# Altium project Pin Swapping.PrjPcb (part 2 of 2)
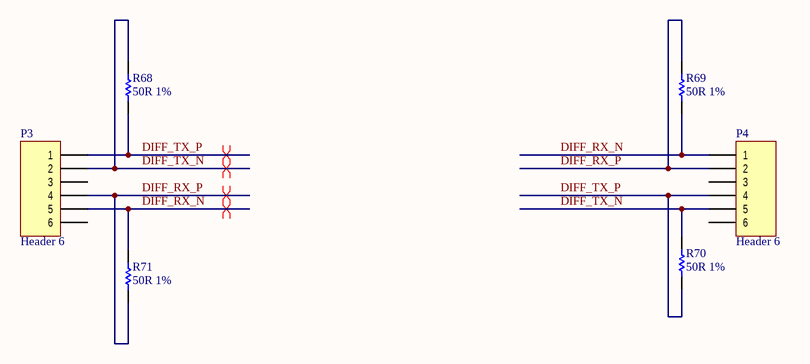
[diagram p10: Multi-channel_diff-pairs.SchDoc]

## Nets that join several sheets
+5V: TOP_SHEET (6 pins), FPGA (HDR1.97 HDR1.99 HDR2.97 HDR2.99)
GND: TOP_SHEET (14 pins), PROCESSOR (72 pins), PROCESSOR_MEMORIES (38 pins), FPGA (112 pins), FPGA_MEMORIES (14 pins)
VCC1V2: TOP_SHEET (5 pins), FPGA (26 pins)
VCC1V8: TOP_SHEET (C132.1 C133.1), PROCESSOR (22 pins), FPGA (5 pins)
VCC2V5: TOP_SHEET (8 pins), FPGA (18 pins)
VCC3V3: TOP_SHEET (C126.1 C127.1), PROCESSOR (75 pins), PROCESSOR_MEMORIES (37 pins), FPGA (77 pins), FPGA_MEMORIES (14 pins)
A0: PROCESSOR (U5.32), PROCESSOR_MEMORIES (U7.H7 U9.H7), FPGA (U1.H2)
A1: PROCESSOR (U5.31), PROCESSOR_MEMORIES (U7.H8 U8.G2 U9.H8), FPGA (U1.R19)
A2: PROCESSOR (U5.30), PROCESSOR_MEMORIES (U7.J8 U8.F2 U9.J8), FPGA (U1.P19)
A3: PROCESSOR (U5.29), PROCESSOR_MEMORIES (U7.J7 U8.E2 U9.J7), FPGA (U1.N18)
A4: PROCESSOR (U5.27), PROCESSOR_MEMORIES (U7.J3 U8.C2 U9.J3), FPGA (U1.K17)
A5: PROCESSOR (U5.26), PROCESSOR_MEMORIES (U7.J2 U8.D2 U9.J2), FPGA (U1.N21)
A6: PROCESSOR (U5.25), PROCESSOR_MEMORIES (U7.H3 U8.F3 U9.H3), FPGA (U1.P18)
A7: PROCESSOR (U5.24), PROCESSOR_MEMORIES (U7.H2 U8.E3 U9.H2), FPGA (U1.P22)
A8: PROCESSOR (U5.22), PROCESSOR_MEMORIES (U7.H1 U8.C3 U9.H1), FPGA (U1.L20)
A9: PROCESSOR (U5.21), PROCESSOR_MEMORIES (U7.G3 U8.D6 U9.G3), FPGA (U1.N20)
A10: PROCESSOR (U5.20), PROCESSOR_MEMORIES (U7.H9 U8.C6 U9.H9), FPGA (U1.K4)
A11: PROCESSOR (U5.19), PROCESSOR_MEMORIES (U7.G2 U8.E6 U9.G2), FPGA (U1.M2)
A12: PROCESSOR (U5.17), PROCESSOR_MEMORIES (U7.G1 U8.F6 U9.G1), FPGA (U1.N5)
A13: PROCESSOR (U5.16), PROCESSOR_MEMORIES (U7.G7 U8.D7 U9.G7), FPGA (U1.N17)
A14: PROCESSOR (U5.15), PROCESSOR_MEMORIES (U7.G8 U8.C7 U9.G8), FPGA (U1.N22)
A15: PROCESSOR (U5.14), PROCESSOR_MEMORIES (U8.E7), FPGA (U1.M6)
A16: PROCESSOR (U5.12), PROCESSOR_MEMORIES (U8.F7), FPGA (U1.P17)
A17: PROCESSOR (U5.11), PROCESSOR_MEMORIES (U8.G7), FPGA (U1.T19)
A18: PROCESSOR (U5.10), PROCESSOR_MEMORIES (U8.D3), FPGA (U1.M18)
A19: PROCESSOR (U5.9), PROCESSOR_MEMORIES (U8.E4), FPGA (U1.P21)
A20: PROCESSOR (U5.7), PROCESSOR_MEMORIES (U8.F5), FPGA (U1.R21)
A21: PROCESSOR (U5.6), PROCESSOR_MEMORIES (U8.F4), FPGA (U1.R22)
A22: PROCESSOR (U5.5), PROCESSOR_MEMORIES (U8.E5), FPGA (U1.N19)
A23: PROCESSOR (U5.4), FPGA (U1.F16)
A24: PROCESSOR (U5.3), FPGA (U1.D18)
A25: PROCESSOR (U5.2), FPGA (U1.F12)
CLK_RTC: PROCESSOR (R44.2), FPGA (U1.J18)
CLKIN: PROCESSOR (R36.2), FPGA (U1.J17)
CLKOUT: PROCESSOR (U5.156), FPGA (U1.D22)
D0: PROCESSOR (U5.87), PROCESSOR_MEMORIES (U8.G3 U9.A8), FPGA (U1.R18)
D1: PROCESSOR (U5.86), PROCESSOR_MEMORIES (U8.K3 U9.B9), FPGA (U1.V22)
D2: PROCESSOR (U5.84), PROCESSOR_MEMORIES (U8.G4 U9.B8), FPGA (U1.T22)
D3: PROCESSOR (U5.83), PROCESSOR_MEMORIES (U8.K4 U9.C9), FPGA (U1.V21)
D4: PROCESSOR (U5.82), PROCESSOR_MEMORIES (U8.K5 U9.C8), FPGA (U1.U14)
D5: PROCESSOR (U5.81), PROCESSOR_MEMORIES (U8.G5 U9.D9), FPGA (U1.T21)
D6: PROCESSOR (U5.79), PROCESSOR_MEMORIES (U8.K6 U9.D8), FPGA (U1.V20)
D7: PROCESSOR (U5.78), PROCESSOR_MEMORIES (U8.G6 U9.E9), FPGA (U1.T20)
D8: PROCESSOR (U5.77), PROCESSOR_MEMORIES (U8.H3 U9.E1), FPGA (U1.T18)
D9: PROCESSOR (U5.76), PROCESSOR_MEMORIES (U8.J3 U9.D2), FPGA (U1.U20)
D10: PROCESSOR (U5.74), PROCESSOR_MEMORIES (U8.H4 U9.D1), FPGA (U1.T17)
D11: PROCESSOR (U5.73), PROCESSOR_MEMORIES (U8.J4 U9.C2), FPGA (U1.U19)
D12: PROCESSOR (U5.72), PROCESSOR_MEMORIES (U8.H5 U9.C1), FPGA (U1.R4)
D13: PROCESSOR (U5.71), PROCESSOR_MEMORIES (U8.J6 U9.B2), FPGA (U1.P6)
D14: PROCESSOR (U5.69), PROCESSOR_MEMORIES (U8.H6 U9.B1), FPGA (U1.U21)
D15: PROCESSOR (U5.68), PROCESSOR_MEMORIES (U8.J7 U9.A2), FPGA (U1.U18)
D16: PROCESSOR (U5.67), PROCESSOR_MEMORIES (U7.A8), FPGA (U1.K19)
D17: PROCESSOR (U5.66), PROCESSOR_MEMORIES (U7.B9), FPGA (U1.M22)
D18: PROCESSOR (U5.65), PROCESSOR_MEMORIES (U7.B8), FPGA (U1.K22)
D19: PROCESSOR (U5.63), PROCESSOR_MEMORIES (U7.C9), FPGA (U1.M19)
D20: PROCESSOR (U5.62), PROCESSOR_MEMORIES (U7.C8), FPGA (U1.K21)
D21: PROCESSOR (U5.61), PROCESSOR_MEMORIES (U7.D9), FPGA (U1.J2)
D22: PROCESSOR (U5.60), PROCESSOR_MEMORIES (U7.D8), FPGA (U1.K6)
D23: PROCESSOR (U5.59), PROCESSOR_MEMORIES (U7.E9), FPGA (U1.M20)
D24: PROCESSOR (U5.58), PROCESSOR_MEMORIES (U7.E1), FPGA (U1.V19)
D25: PROCESSOR (U5.57), PROCESSOR_MEMORIES (U7.D2), FPGA (U1.K5)
D26: PROCESSOR (U5.56), PROCESSOR_MEMORIES (U7.D1), FPGA (U1.K18)
D27: PROCESSOR (U5.54), PROCESSOR_MEMORIES (U7.C2), FPGA (U1.L18)
D28: PROCESSOR (U5.53), PROCESSOR_MEMORIES (U7.C1), FPGA (U1.L17)
D29: PROCESSOR (U5.52), PROCESSOR_MEMORIES (U7.B2), FPGA (U1.K2)
D30: PROCESSOR (U5.51), PROCESSOR_MEMORIES (U7.B1), FPGA (U1.M21)
D31: PROCESSOR (U5.50), PROCESSOR_MEMORIES (U7.A2), FPGA (U1.L22)
FLASH_BUSY: PROCESSOR (R20.1 U5.114), PROCESSOR_MEMORIES (U8.C4)
FPGA_TCK: PROCESSOR (U6.11), FPGA (HDR1.72 R12.1)
FPGA_TMS: PROCESSOR (U6.14), FPGA (HDR1.70 R13.1)
nBLE0: PROCESSOR (U5.37), FPGA (U1.H21)
nBLE1: PROCESSOR (U5.36), FPGA (U1.J6)
nBLE2: PROCESSOR (U5.35), FPGA (U1.J1)
nBLE3: PROCESSOR (U5.34), FPGA (U1.G22)
nCS0: PROCESSOR (U5.48), FPGA (U1.L21)
nCS1: PROCESSOR (U5.47), FPGA (U1.L4)
nCS2: PROCESSOR (U5.46), FPGA (U1.L3)
nCS3: PROCESSOR (U5.44), FPGA (U1.K20)
nCS4: PROCESSOR (U5.43), FPGA (U1.J22)
nCS5: PROCESSOR (U5.42), FPGA (U1.J21)
nFLASH_CS: PROCESSOR (U5.41), PROCESSOR_MEMORIES (U8.H2)
nOE: PROCESSOR (U5.38), PROCESSOR_MEMORIES (U8.J2), FPGA (U1.H22)
nRESETOUT: PROCESSOR (U5.97), PROCESSOR_MEMORIES (U8.D5)
nSDRAM_CAS: PROCESSOR (U5.108), PROCESSOR_MEMORIES (U7.F7 U9.F7)
nSDRAM_CS: PROCESSOR (U5.105), PROCESSOR_MEMORIES (U7.G9 U9.G9)
nSDRAM_RAS: PROCESSOR (U5.107), PROCESSOR_MEMORIES (U7.F8 U9.F8)
nSDRAM_WE: PROCESSOR (U5.106), PROCESSOR_MEMORIES (U7.F9 U9.F9)
nWAIT: PROCESSOR (U5.144), FPGA (U1.J19)
nWE: PROCESSOR (U5.39), PROCESSOR_MEMORIES (U8.C5), FPGA (U1.L19)
PRO_P.SSPCLK: PROCESSOR (U5.165), FPGA (U1.E20)
PRO_P.SSPEN: PROCESSOR (U5.166), FPGA (U1.D21)
PRO_P.SSPFRM: PROCESSOR (U5.164), FPGA (U1.G17)
PRO_P.SSPRX_UART2RX: PROCESSOR (U5.169), FPGA (U1.D17)
PRO_P.SSPTX_UART2TX: PROCESSOR (U5.167), FPGA (U1.C21)
PROCESSOR_TDI: PROCESSOR (U6.3 U6.5), FPGA (R1.2 U1.B22)
PROCESSOR_TDO: PROCESSOR (U6.4), FPGA (R6.1)
SDRAM_CKE: PROCESSOR (U5.102), PROCESSOR_MEMORIES (U7.F3 U9.F3)
SDRAM_CLK: PROCESSOR (U5.101), PROCESSOR_MEMORIES (U7.F2 U9.F2)
SDRAM_DQM0: PROCESSOR (U5.112), PROCESSOR_MEMORIES (U9.E8)
SDRAM_DQM1: PROCESSOR (U5.111), PROCESSOR_MEMORIES (U9.F1)
SDRAM_DQM2: PROCESSOR (U5.110), PROCESSOR_MEMORIES (U7.E8)
SDRAM_DQM3: PROCESSOR (U5.109), PROCESSOR_MEMORIES (U7.F1)
SRAM0_A0: FPGA (U1.B7), FPGA_MEMORIES (U3.1)
SRAM0_A1: FPGA (U1.A8), FPGA_MEMORIES (U3.2)
SRAM0_A2: FPGA (U1.F6), FPGA_MEMORIES (U3.3)
SRAM0_A3: FPGA (U1.J5), FPGA_MEMORIES (U3.4)
SRAM0_A4: FPGA (U1.B9), FPGA_MEMORIES (U3.5)
SRAM0_A5: FPGA (U1.A18), FPGA_MEMORIES (U3.18)
SRAM0_A6: FPGA (U1.C17), FPGA_MEMORIES (U3.19)
SRAM0_A7: FPGA (U1.B18), FPGA_MEMORIES (U3.20)
SRAM0_A8: FPGA (U1.B17), FPGA_MEMORIES (U3.21)
SRAM0_A9: FPGA (U1.E15), FPGA_MEMORIES (U3.22)
SRAM0_A10: FPGA (U1.A13), FPGA_MEMORIES (U3.23)
SRAM0_A11: FPGA (U1.B12), FPGA_MEMORIES (U3.24)
SRAM0_A12: FPGA (U1.D11), FPGA_MEMORIES (U3.25)
SRAM0_A13: FPGA (U1.A12), FPGA_MEMORIES (U3.26)
SRAM0_A14: FPGA (U1.C11), FPGA_MEMORIES (U3.27)
SRAM0_A15: FPGA (U1.D4), FPGA_MEMORIES (U3.42)
SRAM0_A16: FPGA (U1.B4), FPGA_MEMORIES (U3.43)
SRAM0_A17: FPGA (U1.H1), FPGA_MEMORIES (U3.44)
SRAM0_A18: FPGA (U1.B10), FPGA_MEMORIES (U3.28)
SRAM0_D0: FPGA (U1.E9), FPGA_MEMORIES (U3.7)
SRAM0_D1: FPGA (U1.F9), FPGA_MEMORIES (U3.8)
SRAM0_D2: FPGA (U1.E10), FPGA_MEMORIES (U3.9)
SRAM0_D3: FPGA (U1.F10), FPGA_MEMORIES (U3.10)
SRAM0_D4: FPGA (U1.E12), FPGA_MEMORIES (U3.13)
SRAM0_D5: FPGA (U1.B15), FPGA_MEMORIES (U3.14)
SRAM0_D6: FPGA (U1.A16), FPGA_MEMORIES (U3.15)
SRAM0_D7: FPGA (U1.D14), FPGA_MEMORIES (U3.16)
SRAM0_D8: FPGA (U1.A11), FPGA_MEMORIES (U3.29)
SRAM0_D9: FPGA (U1.A9), FPGA_MEMORIES (U3.30)
SRAM0_D10: FPGA (U1.D8), FPGA_MEMORIES (U3.31)
SRAM0_D11: FPGA (U1.D7), FPGA_MEMORIES (U3.32)
SRAM0_D12: FPGA (U1.E6), FPGA_MEMORIES (U3.35)
SRAM0_D13: FPGA (U1.C7), FPGA_MEMORIES (U3.36)
SRAM0_D14: FPGA (U1.F5), FPGA_MEMORIES (U3.37)
SRAM0_D15: FPGA (U1.A7), FPGA_MEMORIES (U3.38)
SRAM0_E: FPGA (U1.A10), FPGA_MEMORIES (U3.6)
SRAM0_LB: FPGA (U1.B5), FPGA_MEMORIES (U3.39)
SRAM0_OE: FPGA (U1.A5), FPGA_MEMORIES (U3.41)
SRAM0_UB: FPGA (U1.G2), FPGA_MEMORIES (U3.40)
SRAM0_W: FPGA (U1.B16), FPGA_MEMORIES (U3.17)
SRAM1_A0: FPGA (U1.K1), FPGA_MEMORIES (U4.1)
SRAM1_A1: FPGA (R19.2 U1.L1), FPGA_MEMORIES (U4.2)
SRAM1_A2: FPGA (U1.M1), FPGA_MEMORIES (U4.3)
SRAM1_A3: FPGA (U1.N1), FPGA_MEMORIES (U4.4)
SRAM1_A4: FPGA (U1.P1), FPGA_MEMORIES (U4.5)
SRAM1_A5: FPGA (U1.AA3), FPGA_MEMORIES (U4.18)
SRAM1_A6: FPGA (U1.V3), FPGA_MEMORIES (U4.19)
SRAM1_A7: FPGA (U1.AA4), FPGA_MEMORIES (U4.20)
SRAM1_A8: FPGA (U1.U2), FPGA_MEMORIES (U4.21)
SRAM1_A9: FPGA (U1.Y6), FPGA_MEMORIES (U4.22)
SRAM1_A10: FPGA (U1.AB7), FPGA_MEMORIES (U4.23)
SRAM1_A11: FPGA (U1.W6), FPGA_MEMORIES (U4.24)
SRAM1_A12: FPGA (U1.N3), FPGA_MEMORIES (U4.25)
SRAM1_A13: FPGA (U1.P4), FPGA_MEMORIES (U4.26)
SRAM1_A14: FPGA (U1.R5), FPGA_MEMORIES (U4.27)
SRAM1_A15: FPGA (U1.AB12), FPGA_MEMORIES (U4.42)
SRAM1_A16: FPGA (U1.Y10), FPGA_MEMORIES (U4.43)
SRAM1_A17: FPGA (U1.AB11), FPGA_MEMORIES (U4.44)
SRAM1_A18: FPGA (U1.L2), FPGA_MEMORIES (U4.28)
SRAM1_D0: FPGA (U1.R1), FPGA_MEMORIES (U4.7)
SRAM1_D1: FPGA (U1.T1), FPGA_MEMORIES (U4.8)
SRAM1_D2: FPGA (U1.T2), FPGA_MEMORIES (U4.9)
SRAM1_D3: FPGA (U1.V7), FPGA_MEMORIES (U4.10)
SRAM1_D4: FPGA (U1.V2), FPGA_MEMORIES (U4.13)
SRAM1_D5: FPGA (U1.V1), FPGA_MEMORIES (U4.14)
SRAM1_D6: FPGA (U1.W1), FPGA_MEMORIES (U4.15)
SRAM1_D7: FPGA (U1.Y1), FPGA_MEMORIES (U4.16)
SRAM1_D8: FPGA (U1.AB9), FPGA_MEMORIES (U4.29)
SRAM1_D9: FPGA (U1.N4), FPGA_MEMORIES (U4.30)
SRAM1_D10: FPGA (U1.T6), FPGA_MEMORIES (U4.31)
SRAM1_D11: FPGA (U1.AA9), FPGA_MEMORIES (U4.32)
SRAM1_D12: FPGA (U1.U7), FPGA_MEMORIES (U4.35)
SRAM1_D13: FPGA (U1.AB15), FPGA_MEMORIES (U4.36)
SRAM1_D14: FPGA (U1.AA14), FPGA_MEMORIES (U4.37)
SRAM1_D15: FPGA (U1.W12), FPGA_MEMORIES (U4.38)
SRAM1_E: FPGA (U1.P2), FPGA_MEMORIES (U4.6)
SRAM1_LB: FPGA (U1.V11), FPGA_MEMORIES (U4.39)
SRAM1_OE: FPGA (U1.N2), FPGA_MEMORIES (U4.41)
SRAM1_UB: FPGA (U1.M5), FPGA_MEMORIES (U4.40)
SRAM1_W: FPGA (U1.W2), FPGA_MEMORIES (U4.17)

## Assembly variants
Assemble 1: not fitted P5
Assemble 2: not fitted P1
